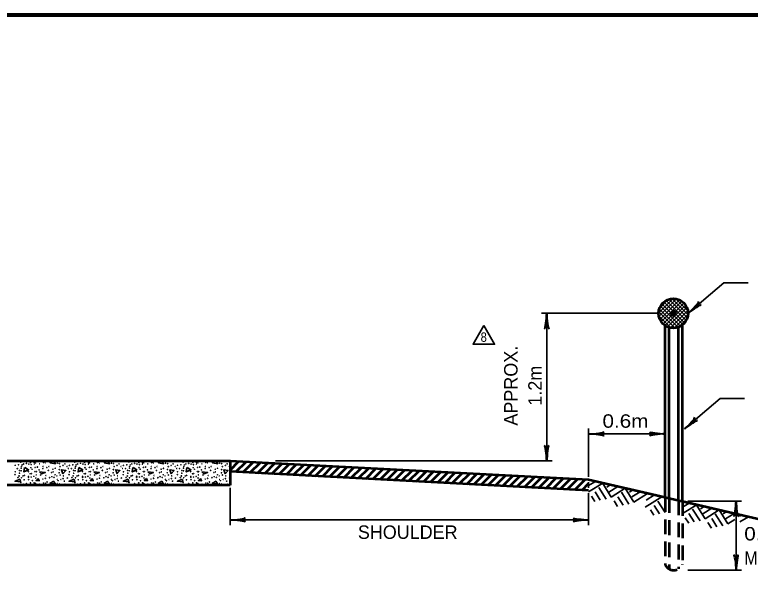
# Model space of a CAD drawing. Extents: x -89 to 766, y -60 to 484.
# Drawn here: x 47 to 211.5, y 351.5 to 478.1 of the extents above; entities that cross this region are included whole.
import ezdxf
from ezdxf.enums import TextEntityAlignment as Align

# ---------------------------------------------------------------- set-up
doc = ezdxf.new("R2010")
doc.units = 0
doc.header["$LTSCALE"] = 1.1
doc.linetypes.add('MEDIUM_DASHED', pattern=[4.5, 3, -1.5])
doc.layers.add('1', color=7, linetype='Continuous', lineweight=35)

msp = doc.modelspace()

# ---------------------------------------------------------------- hatches: boundary and pattern name
at = {"layer": '1'}
msp.add_hatch(color=256, dxfattribs=at).paths.add_polyline_path([(194.888, 411.351, 1), (193.688, 411.351, 1)])

# ---------------------------------------------------------------- linework, layer by layer
for p, q in [((190.989, 411.385), (194.253, 414.648)), ((191.073, 410.62), (195.019, 414.566)), ((191.17, 412.414), (193.226, 414.47)), ((197.418, 410.324), (193.262, 414.481)), ((197.567, 411.024), (193.96, 414.631)), ((197.536, 411.904), (194.841, 414.598)), ((191.289, 409.988), (195.651, 414.35)), ((195.882, 408.466), (191.403, 412.946)), ((191.597, 409.447), (196.193, 414.043)), ((196.388, 408.81), (191.748, 413.449)), ((191.989, 408.991), (196.648, 413.649)), ((196.813, 409.233), (192.17, 413.876)), ((192.457, 408.61), (197.03, 413.183)), ((197.161, 409.733), (192.672, 414.222)), ((196.792, 413.496), (196.436, 413.853)), ((190.988, 411.351), (164.779, 411.351)), ((165.979, 378.37), (165.979, 411.351)), ((194.584, 408.068), (191.007, 411.645)), ((195.288, 408.212), (191.15, 412.351)), ((193.009, 408.314), (197.325, 412.629)), ((193.661, 408.117), (197.522, 411.978)), ((194.454, 408.061), (197.579, 411.186)), ((193.692, 408.111), (191.049, 410.754)), ((195.547, 408.306), (197.337, 410.096)), ((196.765, 385.489), (204.774, 392.299)), ((204.774, 392.299), (210.224, 392.299)), ((175.343, 374.791), (175.343, 385.591)), ((175.343, 384.391), (192.423, 384.391)), ((105.379, 378.37), (167.179, 378.37)), ((176.876, 373.788), (175.343, 372.83)), ((175.343, 373.591), (175.343, 372.365)), ((178.536, 373.405), (175.343, 371.41)), ((178.419, 373.432), (180.398, 370.265)), ((95.179, 372.37), (95.179, 363.965)), ((177.599, 372.439), (179.277, 369.785)), ((180.196, 373.021), (179.385, 372.494)), ((181.88, 372.633), (179.894, 371.392)), ((183.54, 372.249), (180.398, 370.265)), ((183.54, 372.249), (185.465, 369.169)), ((185.201, 371.866), (184.452, 371.398)), ((175.343, 371.165), (175.343, 363.965)), ((175.969, 370.5), (176.748, 369.285)), ((176.802, 371.441), (177.953, 369.598)), ((181.892, 370.339), (183.044, 368.497)), ((182.689, 371.337), (184.344, 368.689)), ((186.884, 371.477), (184.985, 370.29)), ((188.545, 371.094), (185.465, 369.169)), ((191.749, 370.354), (187.978, 367.998)), ((190.088, 370.738), (188.188, 369.55)), ((181.036, 369.404), (181.809, 368.166)), ((190.014, 368.39), (191.165, 366.548)), ((190.811, 369.388), (192.423, 366.84)), ((197.855, 368.944), (196.323, 367.987)), ((199.516, 368.561), (196.323, 366.566)), ((197.523, 369.348), (209.523, 369.348)), ((199.399, 368.588), (201.377, 365.422)), ((208.323, 369.348), (208.323, 353.933)), ((189.181, 367.449), (189.96, 366.235)), ((198.578, 367.595), (200.257, 364.942)), ((201.176, 368.178), (200.365, 367.651)), ((202.86, 367.789), (200.874, 366.548)), ((204.52, 367.406), (201.377, 365.422)), ((204.52, 367.406), (206.445, 364.326)), ((206.18, 367.022), (205.432, 366.555)), ((95.179, 365.165), (175.343, 365.165)), ((196.948, 365.656), (197.727, 364.442)), ((197.781, 366.597), (198.933, 364.755)), ((202.872, 365.495), (204.023, 363.653)), ((203.669, 366.494), (205.324, 363.846)), ((207.864, 366.634), (205.964, 365.447)), ((207.996, 365.295), (206.445, 364.326)), ((209.525, 366.25), (209.11, 365.992)), ((211.068, 365.894), (209.168, 364.707)), ((202.016, 364.56), (202.789, 363.322)), ((197.523, 353.933), (209.523, 353.933))]:
    msp.add_line(p, q, dxfattribs=at)
at = {"layer": '1', "lineweight": 53}
for p, q in [((192.423, 370.248), (192.423, 408.629)), ((193.323, 370.04), (193.323, 408.195)), ((195.423, 369.555), (195.423, 408.252)), ((196.323, 369.348), (196.323, 408.753)), ((95.179, 378.37), (175.343, 374.191)), ((95.179, 377.989), (95.541, 378.351)), ((95.179, 376.292), (97.154, 378.267)), ((96.483, 375.898), (98.767, 378.183)), ((98.095, 375.814), (100.38, 378.099)), ((99.708, 375.729), (101.993, 378.015)), ((101.32, 375.645), (103.606, 377.931)), ((102.933, 375.56), (105.219, 377.846)), ((104.546, 375.476), (106.832, 377.762)), ((106.158, 375.391), (108.445, 377.678)), ((107.771, 375.307), (110.058, 377.594)), ((109.383, 375.222), (111.671, 377.51)), ((110.996, 375.138), (113.284, 377.426)), ((112.608, 375.053), (114.897, 377.342)), ((114.221, 374.969), (116.51, 377.258)), ((115.833, 374.884), (118.123, 377.174)), ((117.446, 374.8), (119.736, 377.09)), ((119.058, 374.715), (121.349, 377.006)), ((120.671, 374.631), (122.962, 376.922)), ((122.284, 374.546), (124.575, 376.838)), ((123.896, 374.462), (126.188, 376.754)), ((125.509, 374.377), (127.801, 376.669)), ((127.121, 374.293), (129.414, 376.585)), ((175.343, 371.765), (95.179, 375.966)), ((128.734, 374.208), (131.027, 376.501)), ((130.346, 374.124), (132.64, 376.417)), ((131.959, 374.039), (134.253, 376.333)), ((133.571, 373.954), (135.866, 376.249)), ((135.184, 373.87), (137.479, 376.165)), ((136.796, 373.785), (139.092, 376.081)), ((138.409, 373.701), (140.705, 375.997)), ((140.022, 373.616), (142.318, 375.913)), ((141.634, 373.532), (143.931, 375.829)), ((143.247, 373.447), (145.544, 375.745)), ((144.859, 373.363), (147.157, 375.66)), ((146.472, 373.278), (148.77, 375.576)), ((148.084, 373.194), (150.383, 375.492)), ((149.697, 373.109), (151.996, 375.408)), ((151.309, 373.025), (153.609, 375.324)), ((152.922, 372.94), (155.222, 375.24)), ((154.535, 372.856), (156.835, 375.156)), ((156.147, 372.771), (158.448, 375.072)), ((157.76, 372.687), (160.061, 374.988)), ((159.372, 372.602), (161.674, 374.904)), ((160.985, 372.518), (163.286, 374.82)), ((162.597, 372.433), (164.899, 374.736)), ((164.21, 372.349), (166.512, 374.651)), ((165.822, 372.264), (168.125, 374.567)), ((167.435, 372.18), (169.738, 374.483)), ((169.047, 372.095), (171.351, 374.399)), ((170.66, 372.011), (172.964, 374.315)), ((172.273, 371.926), (174.577, 374.231)), ((173.885, 371.842), (175.343, 373.3)), ((175.343, 374.191), (192.423, 370.248)), ((175.343, 374.191), (211.025, 365.953)), ((95.179, 372.97), (-1.421, 372.97))]:
    msp.add_line(p, q, dxfattribs=at)
at = {"layer": '1', "linetype": 'MEDIUM_DASHED', "lineweight": 53}
for p, q in [((192.423, 370.248), (192.423, 355.248)), ((193.323, 370.04), (193.323, 354.214)), ((195.423, 369.555), (195.423, 354.214)), ((196.323, 369.348), (196.323, 355.248))]:
    msp.add_line(p, q, dxfattribs=at)
at = {"layer": '1', "lineweight": 158}
msp.add_lwpolyline([(759.817, 478.083), (-31.883, 477.983), (-31.783, -48.017)], dxfattribs=at)
at = {"layer": '1'}
for points in [[(197.588, 411.351), (205.597, 418.161), (211.047, 418.161)], [(47.241, 378.37), (48.374, 378.239), (48.346, 378.37)], [(59.337, 378.37), (60.47, 378.239), (60.442, 378.37)], [(71.433, 378.37), (72.566, 378.239), (72.538, 378.37)], [(83.529, 378.37), (84.662, 378.239), (84.634, 378.37)], [(49.31, 376.871), (50.15, 376.391), (49.118, 375.887), (49.262, 376.895)], [(61.406, 376.871), (62.246, 376.391), (61.214, 375.887), (61.358, 376.895)], [(73.502, 376.871), (74.342, 376.391), (73.31, 375.887), (73.454, 376.895)], [(85.598, 376.871), (86.438, 376.391), (85.406, 375.887), (85.55, 376.895)], [(57.83, 375.431), (57.542, 376.391), (58.478, 376.199), (57.806, 375.479)], [(69.926, 375.431), (69.638, 376.391), (70.574, 376.199), (69.902, 375.479)], [(82.022, 375.431), (81.734, 376.391), (82.67, 376.199), (81.998, 375.479)], [(94.118, 375.431), (93.83, 376.391), (94.766, 376.199), (94.094, 375.479)], [(48.254, 374.279), (47.126, 373.823), (48.374, 373.679), (48.254, 374.231)], [(52.286, 374.447), (51.83, 373.967), (52.526, 373.919), (52.286, 374.399)], [(55.766, 373.823), (54.974, 373.391), (56.15, 373.175), (55.718, 373.847)], [(60.35, 374.279), (59.222, 373.823), (60.47, 373.679), (60.35, 374.231)], [(64.382, 374.447), (63.926, 373.967), (64.622, 373.919), (64.382, 374.399)], [(67.862, 373.823), (67.07, 373.391), (68.246, 373.175), (67.814, 373.847)], [(72.446, 374.279), (71.318, 373.823), (72.566, 373.679), (72.446, 374.231)], [(76.478, 374.447), (76.022, 373.967), (76.718, 373.919), (76.478, 374.399)], [(79.958, 373.823), (79.166, 373.391), (80.342, 373.175), (79.91, 373.847)], [(84.542, 374.279), (83.414, 373.823), (84.662, 373.679), (84.542, 374.231)], [(88.574, 374.447), (88.118, 373.967), (88.814, 373.919), (88.574, 374.399)], [(92.054, 373.823), (91.262, 373.391), (92.438, 373.175), (92.006, 373.847)]]:
    msp.add_lwpolyline(points, dxfattribs=at)
for points in [[(151.911, 408.603), (149.511, 404.446), (154.311, 404.446)], [(55.742, 378.37), (54.974, 377.951), (56.15, 377.735)], [(67.838, 378.37), (67.07, 377.951), (68.246, 377.735)], [(79.934, 378.37), (79.166, 377.951), (80.342, 377.735)], [(92.03, 378.37), (91.262, 377.951), (92.438, 377.735)], [(52.622, 375.935), (53.87, 375.791), (53.054, 375.503)], [(64.718, 375.935), (65.966, 375.791), (65.15, 375.503)], [(76.814, 375.935), (78.062, 375.791), (77.246, 375.503)], [(88.91, 375.935), (90.158, 375.791), (89.342, 375.503)]]:
    msp.add_lwpolyline(points, close=True, dxfattribs=at)
at = {"layer": '1', "lineweight": 53}
for points in [[(-1.421, 378.37), (95.179, 378.37), (95.179, 375.966), (95.179, 372.97)], [(196.323, 369.348), (211.025, 365.953), (249.131, 357.156)]]:
    msp.add_lwpolyline(points, dxfattribs=at)
msp.add_circle((194.288, 411.351), 3.3, dxfattribs=at)
at = {"layer": '1'}
for centre, radius in [((194.288, 411.351), 0.6), ((54.286, 378.217), 0.0318), ((66.382, 378.217), 0.0318), ((78.478, 378.217), 0.0318), ((90.574, 378.217), 0.0318), ((47.152, 377.374), 0.0318), ((47.613, 376.626), 0.0318), ((47.931, 377.485), 0.0318), ((48.408, 378.073), 0.0318), ((48.487, 376.721), 0.0318), ((48.567, 377.087), 0.0318), ((48.694, 377.469), 0.0318), ((49.028, 377.676), 0.0318), ((49.664, 377.819), 0.0318), ((50.205, 377.644), 0.0318), ((50.587, 377.994), 0.0318), ((50.65, 376.849), 0.0318), ((50.714, 377.517), 0.0318), ((51.414, 378.01), 0.0318), ((51.43, 377.628), 0.0318), ((51.621, 376.912), 0.0318), ((51.693, 377.914), 0.0318), ((52.123, 376.976), 0.0318), ((52.632, 377.708), 0.0318), ((53.331, 376.626), 0.0318), ((53.395, 377.103), 0.0318), ((53.49, 377.978), 0.0318), ((53.904, 377.93), 0.0318), ((54.222, 376.849), 0.0318), ((54.699, 377.103), 0.0318), ((56.099, 376.705), 0.0318), ((56.576, 377.867), 0.0318), ((57.037, 377.755), 0.0318), ((57.18, 377.071), 0.0318), ((57.832, 377.358), 0.0318), ((58.277, 377.692), 0.0318), ((58.755, 377.103), 0.0318), ((59.089, 376.658), 0.0318), ((59.248, 377.374), 0.0318), ((59.709, 376.626), 0.0318), ((60.027, 377.485), 0.0318), ((60.504, 378.073), 0.0318), ((60.583, 376.721), 0.0318), ((60.663, 377.087), 0.0318), ((60.79, 377.469), 0.0318), ((61.124, 377.676), 0.0318), ((61.76, 377.819), 0.0318), ((62.301, 377.644), 0.0318), ((62.683, 377.994), 0.0318), ((62.746, 376.849), 0.0318), ((62.81, 377.517), 0.0318), ((63.51, 378.01), 0.0318), ((63.526, 377.628), 0.0318), ((63.717, 376.912), 0.0318), ((63.789, 377.914), 0.0318), ((64.219, 376.976), 0.0318), ((64.728, 377.708), 0.0318), ((65.427, 376.626), 0.0318), ((65.491, 377.103), 0.0318), ((65.586, 377.978), 0.0318), ((66, 377.93), 0.0318), ((66.318, 376.849), 0.0318), ((66.795, 377.103), 0.0318), ((68.195, 376.705), 0.0318), ((68.672, 377.867), 0.0318), ((69.133, 377.755), 0.0318), ((69.276, 377.071), 0.0318), ((69.928, 377.358), 0.0318), ((70.373, 377.692), 0.0318), ((70.851, 377.103), 0.0318), ((71.185, 376.658), 0.0318), ((71.344, 377.374), 0.0318), ((71.805, 376.626), 0.0318), ((72.123, 377.485), 0.0318), ((72.6, 378.073), 0.0318), ((72.679, 376.721), 0.0318), ((72.759, 377.087), 0.0318), ((72.886, 377.469), 0.0318), ((73.22, 377.676), 0.0318), ((73.856, 377.819), 0.0318), ((74.397, 377.644), 0.0318), ((74.779, 377.994), 0.0318), ((74.842, 376.849), 0.0318), ((74.906, 377.517), 0.0318), ((75.606, 378.01), 0.0318), ((75.622, 377.628), 0.0318), ((75.813, 376.912), 0.0318), ((75.885, 377.914), 0.0318), ((76.315, 376.976), 0.0318), ((76.824, 377.708), 0.0318), ((77.523, 376.626), 0.0318), ((77.587, 377.103), 0.0318), ((77.682, 377.978), 0.0318), ((78.096, 377.93), 0.0318), ((78.414, 376.849), 0.0318), ((78.891, 377.103), 0.0318), ((80.291, 376.705), 0.0318), ((80.768, 377.867), 0.0318), ((81.229, 377.755), 0.0318), ((81.372, 377.071), 0.0318), ((82.024, 377.358), 0.0318), ((82.469, 377.692), 0.0318), ((82.947, 377.103), 0.0318), ((83.281, 376.658), 0.0318), ((83.44, 377.374), 0.0318), ((83.901, 376.626), 0.0318), ((84.219, 377.485), 0.0318), ((84.696, 378.073), 0.0318), ((84.775, 376.721), 0.0318), ((84.855, 377.087), 0.0318), ((84.982, 377.469), 0.0318), ((85.316, 377.676), 0.0318), ((85.952, 377.819), 0.0318), ((86.493, 377.644), 0.0318), ((86.875, 377.994), 0.0318), ((86.938, 376.849), 0.0318), ((87.002, 377.517), 0.0318), ((87.702, 378.01), 0.0318), ((87.718, 377.628), 0.0318), ((87.909, 376.912), 0.0318), ((87.981, 377.914), 0.0318), ((88.411, 376.976), 0.0318), ((88.92, 377.708), 0.0318), ((89.619, 376.626), 0.0318), ((89.683, 377.103), 0.0318), ((89.778, 377.978), 0.0318), ((90.192, 377.93), 0.0318), ((90.51, 376.849), 0.0318), ((90.987, 377.103), 0.0318), ((92.387, 376.705), 0.0318), ((92.864, 377.867), 0.0318), ((93.325, 377.755), 0.0318), ((93.468, 377.071), 0.0318), ((94.12, 377.358), 0.0318), ((94.565, 377.692), 0.0318), ((95.043, 377.103), 0.0318), ((47.104, 375.274), 0.0318), ((47.183, 375.926), 0.0318), ((48.026, 375.003), 0.0318), ((48.122, 376.228), 0.0318), ((48.138, 375.608), 0.0318), ((48.472, 376.149), 0.0318), ((48.869, 374.971), 0.0318), ((49.203, 375.114), 0.0318), ((50.094, 375.974), 0.0318), ((50.142, 374.892), 0.0318), ((50.491, 375.496), 0.0318), ((50.762, 375.496), 0.0318), ((50.921, 376.498), 0.0318), ((51.318, 374.908), 0.0318), ((51.597, 375.939), 0.0318), ((51.868, 375.958), 0.0318), ((51.868, 375.242), 0.0318), ((52.52, 376.355), 0.0318), ((52.838, 375.194), 0.0318), ((54.031, 375.099), 0.0318), ((54.556, 376.228), 0.0318), ((55.272, 375.735), 0.0318), ((55.606, 376.498), 0.0318), ((55.653, 375.91), 0.0318), ((56.067, 375.258), 0.0318), ((56.496, 375.019), 0.0318), ((56.973, 375.703), 0.0318), ((57.021, 376.419), 0.0318), ((57.196, 375.194), 0.0318), ((57.975, 375.019), 0.0318), ((59.2, 375.274), 0.0318), ((59.279, 375.926), 0.0318), ((60.122, 375.003), 0.0318), ((60.218, 376.228), 0.0318), ((60.234, 375.608), 0.0318), ((60.568, 376.149), 0.0318), ((60.965, 374.971), 0.0318), ((61.299, 375.114), 0.0318), ((62.19, 375.974), 0.0318), ((62.238, 374.892), 0.0318), ((62.587, 375.496), 0.0318), ((62.858, 375.496), 0.0318), ((63.017, 376.498), 0.0318), ((63.414, 374.908), 0.0318), ((63.693, 375.939), 0.0318), ((63.964, 375.958), 0.0318), ((63.964, 375.242), 0.0318), ((64.616, 376.355), 0.0318), ((64.934, 375.194), 0.0318), ((66.127, 375.099), 0.0318), ((66.652, 376.228), 0.0318), ((67.368, 375.735), 0.0318), ((67.702, 376.498), 0.0318), ((67.749, 375.91), 0.0318), ((68.163, 375.258), 0.0318), ((68.592, 375.019), 0.0318), ((69.069, 375.703), 0.0318), ((69.117, 376.419), 0.0318), ((69.292, 375.194), 0.0318), ((70.071, 375.019), 0.0318), ((71.296, 375.274), 0.0318), ((71.375, 375.926), 0.0318), ((72.218, 375.003), 0.0318), ((72.314, 376.228), 0.0318), ((72.33, 375.608), 0.0318), ((72.664, 376.149), 0.0318), ((73.061, 374.971), 0.0318), ((73.395, 375.114), 0.0318), ((74.286, 375.974), 0.0318), ((74.334, 374.892), 0.0318), ((74.683, 375.496), 0.0318), ((74.954, 375.496), 0.0318), ((75.113, 376.498), 0.0318), ((75.51, 374.908), 0.0318), ((75.789, 375.939), 0.0318), ((76.06, 375.958), 0.0318), ((76.06, 375.242), 0.0318), ((76.712, 376.355), 0.0318), ((77.03, 375.194), 0.0318), ((78.223, 375.099), 0.0318), ((78.748, 376.228), 0.0318), ((79.464, 375.735), 0.0318), ((79.798, 376.498), 0.0318), ((79.845, 375.91), 0.0318), ((80.259, 375.258), 0.0318), ((80.688, 375.019), 0.0318), ((81.165, 375.703), 0.0318), ((81.213, 376.419), 0.0318), ((81.388, 375.194), 0.0318), ((82.167, 375.019), 0.0318), ((83.392, 375.274), 0.0318), ((83.471, 375.926), 0.0318), ((84.314, 375.003), 0.0318), ((84.41, 376.228), 0.0318), ((84.426, 375.608), 0.0318), ((84.76, 376.149), 0.0318), ((85.157, 374.971), 0.0318), ((85.491, 375.114), 0.0318), ((86.382, 375.974), 0.0318), ((86.43, 374.892), 0.0318), ((86.779, 375.496), 0.0318), ((87.05, 375.496), 0.0318), ((87.209, 376.498), 0.0318), ((87.606, 374.908), 0.0318), ((87.885, 375.939), 0.0318), ((88.156, 375.958), 0.0318), ((88.156, 375.242), 0.0318), ((88.808, 376.355), 0.0318), ((89.126, 375.194), 0.0318), ((90.319, 375.099), 0.0318), ((90.844, 376.228), 0.0318), ((91.56, 375.735), 0.0318), ((91.894, 376.498), 0.0318), ((91.941, 375.91), 0.0318), ((92.355, 375.258), 0.0318), ((92.784, 375.019), 0.0318), ((93.261, 375.703), 0.0318), ((93.309, 376.419), 0.0318), ((93.484, 375.194), 0.0318), ((94.263, 375.019), 0.0318), ((47.772, 374.627), 0.0318), ((48.408, 373.513), 0.0318), ((48.535, 374.579), 0.0318), ((49.171, 374.134), 0.0318), ((49.664, 373.259), 0.0318), ((50.126, 374.691), 0.0318), ((50.173, 374.15), 0.0318), ((50.587, 373.434), 0.0318), ((50.73, 374.754), 0.0318), ((50.984, 373.927), 0.0318), ((51.414, 373.45), 0.0318), ((51.693, 373.354), 0.0318), ((51.757, 374.532), 0.0318), ((53.363, 374.277), 0.0318), ((53.49, 373.418), 0.0318), ((53.904, 374.484), 0.0318), ((53.904, 373.37), 0.0318), ((54.286, 373.657), 0.0318), ((54.874, 374.595), 0.0318), ((55.351, 374.828), 0.0318), ((55.828, 374.675), 0.0318), ((56.576, 374.198), 0.0318), ((56.576, 373.307), 0.0318), ((56.767, 373.943), 0.0318), ((57.387, 374.198), 0.0318), ((57.864, 374.389), 0.0318), ((58.134, 373.832), 0.0318), ((58.198, 373.832), 0.0318), ((58.802, 374.516), 0.0318), ((59.868, 374.627), 0.0318), ((60.504, 373.513), 0.0318), ((60.631, 374.579), 0.0318), ((61.267, 374.134), 0.0318), ((61.76, 373.259), 0.0318), ((62.222, 374.691), 0.0318), ((62.269, 374.15), 0.0318), ((62.683, 373.434), 0.0318), ((62.826, 374.754), 0.0318), ((63.08, 373.927), 0.0318), ((63.51, 373.45), 0.0318), ((63.789, 373.354), 0.0318), ((63.853, 374.532), 0.0318), ((65.459, 374.277), 0.0318), ((65.586, 373.418), 0.0318), ((66, 374.484), 0.0318), ((66, 373.37), 0.0318), ((66.382, 373.657), 0.0318), ((66.97, 374.595), 0.0318), ((67.447, 374.828), 0.0318), ((67.924, 374.675), 0.0318), ((68.672, 374.198), 0.0318), ((68.672, 373.307), 0.0318), ((68.863, 373.943), 0.0318), ((69.483, 374.198), 0.0318), ((69.96, 374.389), 0.0318), ((70.23, 373.832), 0.0318), ((70.294, 373.832), 0.0318), ((70.898, 374.516), 0.0318), ((71.964, 374.627), 0.0318), ((72.6, 373.513), 0.0318), ((72.727, 374.579), 0.0318), ((73.363, 374.134), 0.0318), ((73.856, 373.259), 0.0318), ((74.318, 374.691), 0.0318), ((74.365, 374.15), 0.0318), ((74.779, 373.434), 0.0318), ((74.922, 374.754), 0.0318), ((75.176, 373.927), 0.0318), ((75.606, 373.45), 0.0318), ((75.885, 373.354), 0.0318), ((75.949, 374.532), 0.0318), ((77.555, 374.277), 0.0318), ((77.682, 373.418), 0.0318), ((78.096, 374.484), 0.0318), ((78.096, 373.37), 0.0318), ((78.478, 373.657), 0.0318), ((79.066, 374.595), 0.0318), ((79.543, 374.828), 0.0318), ((80.02, 374.675), 0.0318), ((80.768, 374.198), 0.0318), ((80.768, 373.307), 0.0318), ((80.959, 373.943), 0.0318), ((81.579, 374.198), 0.0318), ((82.056, 374.389), 0.0318), ((82.326, 373.832), 0.0318), ((82.39, 373.832), 0.0318), ((82.994, 374.516), 0.0318), ((84.06, 374.627), 0.0318), ((84.696, 373.513), 0.0318), ((84.823, 374.579), 0.0318), ((85.459, 374.134), 0.0318), ((85.952, 373.259), 0.0318), ((86.414, 374.691), 0.0318), ((86.461, 374.15), 0.0318), ((86.875, 373.434), 0.0318), ((87.018, 374.754), 0.0318), ((87.272, 373.927), 0.0318), ((87.702, 373.45), 0.0318), ((87.981, 373.354), 0.0318), ((88.045, 374.532), 0.0318), ((89.651, 374.277), 0.0318), ((89.778, 373.418), 0.0318), ((90.192, 374.484), 0.0318), ((90.192, 373.37), 0.0318), ((90.574, 373.657), 0.0318), ((91.162, 374.595), 0.0318), ((91.639, 374.828), 0.0318), ((92.116, 374.675), 0.0318), ((92.864, 374.198), 0.0318), ((92.864, 373.307), 0.0318), ((93.055, 373.943), 0.0318), ((93.675, 374.198), 0.0318), ((94.152, 374.389), 0.0318), ((94.422, 373.832), 0.0318), ((94.486, 373.832), 0.0318), ((95.09, 374.516), 0.0318), ((49.028, 373.116), 0.0318), ((50.205, 373.084), 0.0318), ((51.43, 373.068), 0.0318), ((52.632, 373.148), 0.0318), ((57.037, 373.195), 0.0318), ((58.277, 373.132), 0.0318), ((61.124, 373.116), 0.0318), ((62.301, 373.084), 0.0318), ((63.526, 373.068), 0.0318), ((64.728, 373.148), 0.0318), ((69.133, 373.195), 0.0318), ((70.373, 373.132), 0.0318), ((73.22, 373.116), 0.0318), ((74.397, 373.084), 0.0318), ((75.622, 373.068), 0.0318), ((76.824, 373.148), 0.0318), ((81.229, 373.195), 0.0318), ((82.469, 373.132), 0.0318), ((85.316, 373.116), 0.0318), ((86.493, 373.084), 0.0318), ((87.718, 373.068), 0.0318), ((88.92, 373.148), 0.0318), ((93.325, 373.195), 0.0318), ((94.565, 373.132), 0.0318)]:
    msp.add_circle(centre, radius, dxfattribs=at)
for centre, start, end in [((58.134, 378.392), 223.38683, 316.61317), ((58.198, 378.392), 223.38683, 316.61317), ((70.23, 378.392), 223.38683, 316.61317), ((70.294, 378.392), 223.38683, 316.61317), ((82.326, 378.392), 223.38683, 316.61317), ((82.39, 378.392), 223.38683, 316.61317), ((94.422, 378.392), 223.38683, 316.61317), ((94.486, 378.392), 223.38683, 316.61317), ((50.714, 372.957), 24.63166, 155.36834), ((62.81, 372.957), 24.63166, 155.36834), ((74.906, 372.957), 24.63166, 155.36834), ((87.002, 372.957), 24.63166, 155.36834)]:
    msp.add_arc(centre, 0.0318, start, end, dxfattribs=at)
at = {"layer": '1', "linetype": 'MEDIUM_DASHED', "lineweight": 53}
msp.add_arc((194.373, 356.036), 2.103, 202.01371, 337.98629, dxfattribs=at)
at = {"layer": '1', "lineweight": 40}
for centre, major_axis, ratio, start_param, end_param in [((198.371, 412.452), (-1.511, -1.531), 0.122415, 0.8963533, 3.1415927), ((198.371, 412.452), (-1.511, -1.531), 0.122415, 0.8963533, 3.1415927), ((198.777, 412.028), (-1.742, -1.205), 0.07063, 3.1407148, 5.41811), ((198.777, 412.028), (-1.742, -1.205), 0.07063, 3.1407148, 5.41811), ((165.725, 410.006), (0.211, 2.108), 0.07063, 3.1407148, 5.41811), ((166.311, 410.041), (-0.187, 2.143), 0.122415, 0.8963533, 3.1415927), ((197.548, 386.589), (-1.511, -1.531), 0.122415, 0.8963533, 3.1415927), ((197.548, 386.589), (-1.511, -1.531), 0.122415, 0.8963533, 3.1415927), ((197.954, 386.166), (-1.742, -1.205), 0.07063, 3.1407148, 5.41811), ((197.954, 386.166), (-1.742, -1.205), 0.07063, 3.1407148, 5.41811), ((176.653, 384.723), (-2.143, -0.187), 0.122415, 0.8963533, 3.1415927), ((176.653, 384.723), (-2.143, -0.187), 0.122415, 0.8963533, 3.1415927), ((191.078, 384.645), (2.108, -0.211), 0.07063, 3.1407148, 5.41811), ((176.688, 384.137), (-2.108, 0.211), 0.07063, 3.1407148, 5.41811), ((176.688, 384.137), (-2.108, 0.211), 0.07063, 3.1407148, 5.41811), ((191.113, 384.06), (2.143, 0.187), 0.122415, 0.8963533, 3.1415927), ((165.647, 379.679), (0.187, -2.143), 0.122415, 0.8963533, 3.1415927), ((166.233, 379.715), (-0.211, -2.108), 0.07063, 3.1407148, 5.41811), ((208.069, 368.003), (0.211, 2.108), 0.07063, 3.1407148, 5.41811), ((208.069, 368.003), (0.211, 2.108), 0.07063, 3.1407148, 5.41811), ((208.654, 368.038), (-0.187, 2.143), 0.122415, 0.8963533, 3.1415927), ((208.654, 368.038), (-0.187, 2.143), 0.122415, 0.8963533, 3.1415927), ((96.488, 365.497), (-2.143, -0.187), 0.122415, 0.8963533, 3.1415927), ((96.488, 365.497), (-2.143, -0.187), 0.122415, 0.8963533, 3.1415927), ((96.524, 364.911), (-2.108, 0.211), 0.07063, 3.1407148, 5.41811), ((96.524, 364.911), (-2.108, 0.211), 0.07063, 3.1407148, 5.41811), ((174.034, 364.834), (2.143, 0.187), 0.122415, 0.8963533, 3.1415927), ((173.998, 365.419), (2.108, -0.211), 0.07063, 3.1407148, 5.41811), ((207.991, 355.242), (0.187, -2.143), 0.122415, 0.8963533, 3.1415927), ((208.577, 355.278), (-0.211, -2.108), 0.07063, 3.1407148, 5.41811)]:
    msp.add_ellipse(centre, major_axis=major_axis, ratio=ratio, start_param=start_param, end_param=end_param, dxfattribs=at)

# ---------------------------------------------------------------- texts
at = {"layer": '1'}
for s, height, width, p in [('8', 2.1, 0.9, (151.195, 404.971)), ('0.6m', 3, 1.15, (178.448, 385.772)), ('0.6m', 3, 1.15, (210.14, 360.575)), ('MIN.', 3, 0.9, (210.14, 355.175))]:
    msp.add_text(s, height=height, dxfattribs=dict(at, width=width)).set_placement(p)
for s, p in [('APPROX.', (159.453, 395.166)), ('1.2m', (164.853, 395.166))]:
    msp.add_text(s, height=3, rotation=90, dxfattribs=at).set_placement(p, align=Align.CENTER)
msp.add_text('SHOULDER', height=3, dxfattribs=at).set_placement((123.761, 360.93))

doc.saveas('drawing.dxf')
